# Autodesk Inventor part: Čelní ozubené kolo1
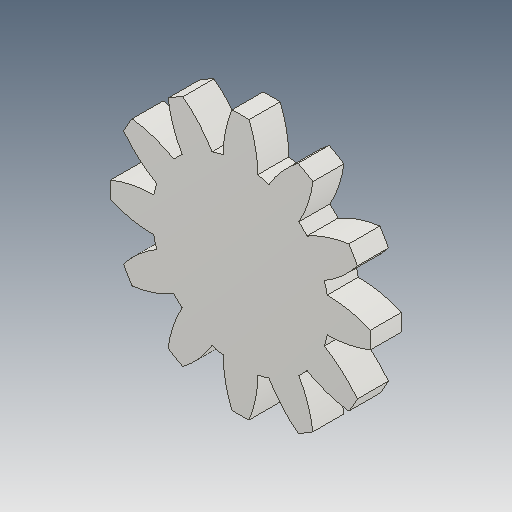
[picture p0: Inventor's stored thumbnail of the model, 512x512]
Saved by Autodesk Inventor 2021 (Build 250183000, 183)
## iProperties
CustomPartVersion: 1
Created: 2024-11
Part Number: Čelní ozubené kolo1
Material: Steel
Document SubType Name: Modeling
Designer: tatulinek
Categories: <?xml version="1.0" encoding="UTF-16"?> <MemberInstance><Categories><FamilyTemplate><FamilyTemplateParameter ValueType="xs:double" Id="1" ObjectReferenceKey="da
Density: 1 g/cm^3
Appearance: Steel
Author: tatulinek
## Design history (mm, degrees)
sketch "Sketch1"
  geometry: C1 r 84 at (0, 0)
  constraints: 1 centre point
  dimensions: "d0" = 168 diameter of C1 (= da_da)
extrude "Extrusion1" new body sketch "Sketch1" distance "d1" = 20 (= da_b); taper "d2" = 0 deg
workplane "Work Plane2"
sketch "Sketch2"
  geometry: C1 r 84 at (0, 0) reference; C2 r 72 at (0, 0)
  constraints: 1 centre point, 1 coincident
  dimensions: "d3" = 144 diameter of C2 (= da_d)
feature "Roztečný průměr" sketch "Sketch2" dims "d4" = 10, "d5" = 0
workplane "Work Plane8"
workplane "Work Plane9"
feature "Čelní ozubené kolo" dims "d5" = 0, "da_b" = 20, "da_d" = 144, "da_aw" = 174, "da_da" = 168, "da_df" = 114, "da_dw" = 144, angle "da_beta" = 0 deg, "da_lefttooth" = 0, "da_righttooth" = 0
body "Solid1"
body "Srf1"
other parameters: "d16" = 174 (= da_aw), "d17" = 0, "d34" = 15 deg (computed from da_z), "d39" = 0, "d41" = 0, "d43" = 174 (= da_aw), "d46" = 174 (= da_aw), "d47" = 0, "d48" = 0
